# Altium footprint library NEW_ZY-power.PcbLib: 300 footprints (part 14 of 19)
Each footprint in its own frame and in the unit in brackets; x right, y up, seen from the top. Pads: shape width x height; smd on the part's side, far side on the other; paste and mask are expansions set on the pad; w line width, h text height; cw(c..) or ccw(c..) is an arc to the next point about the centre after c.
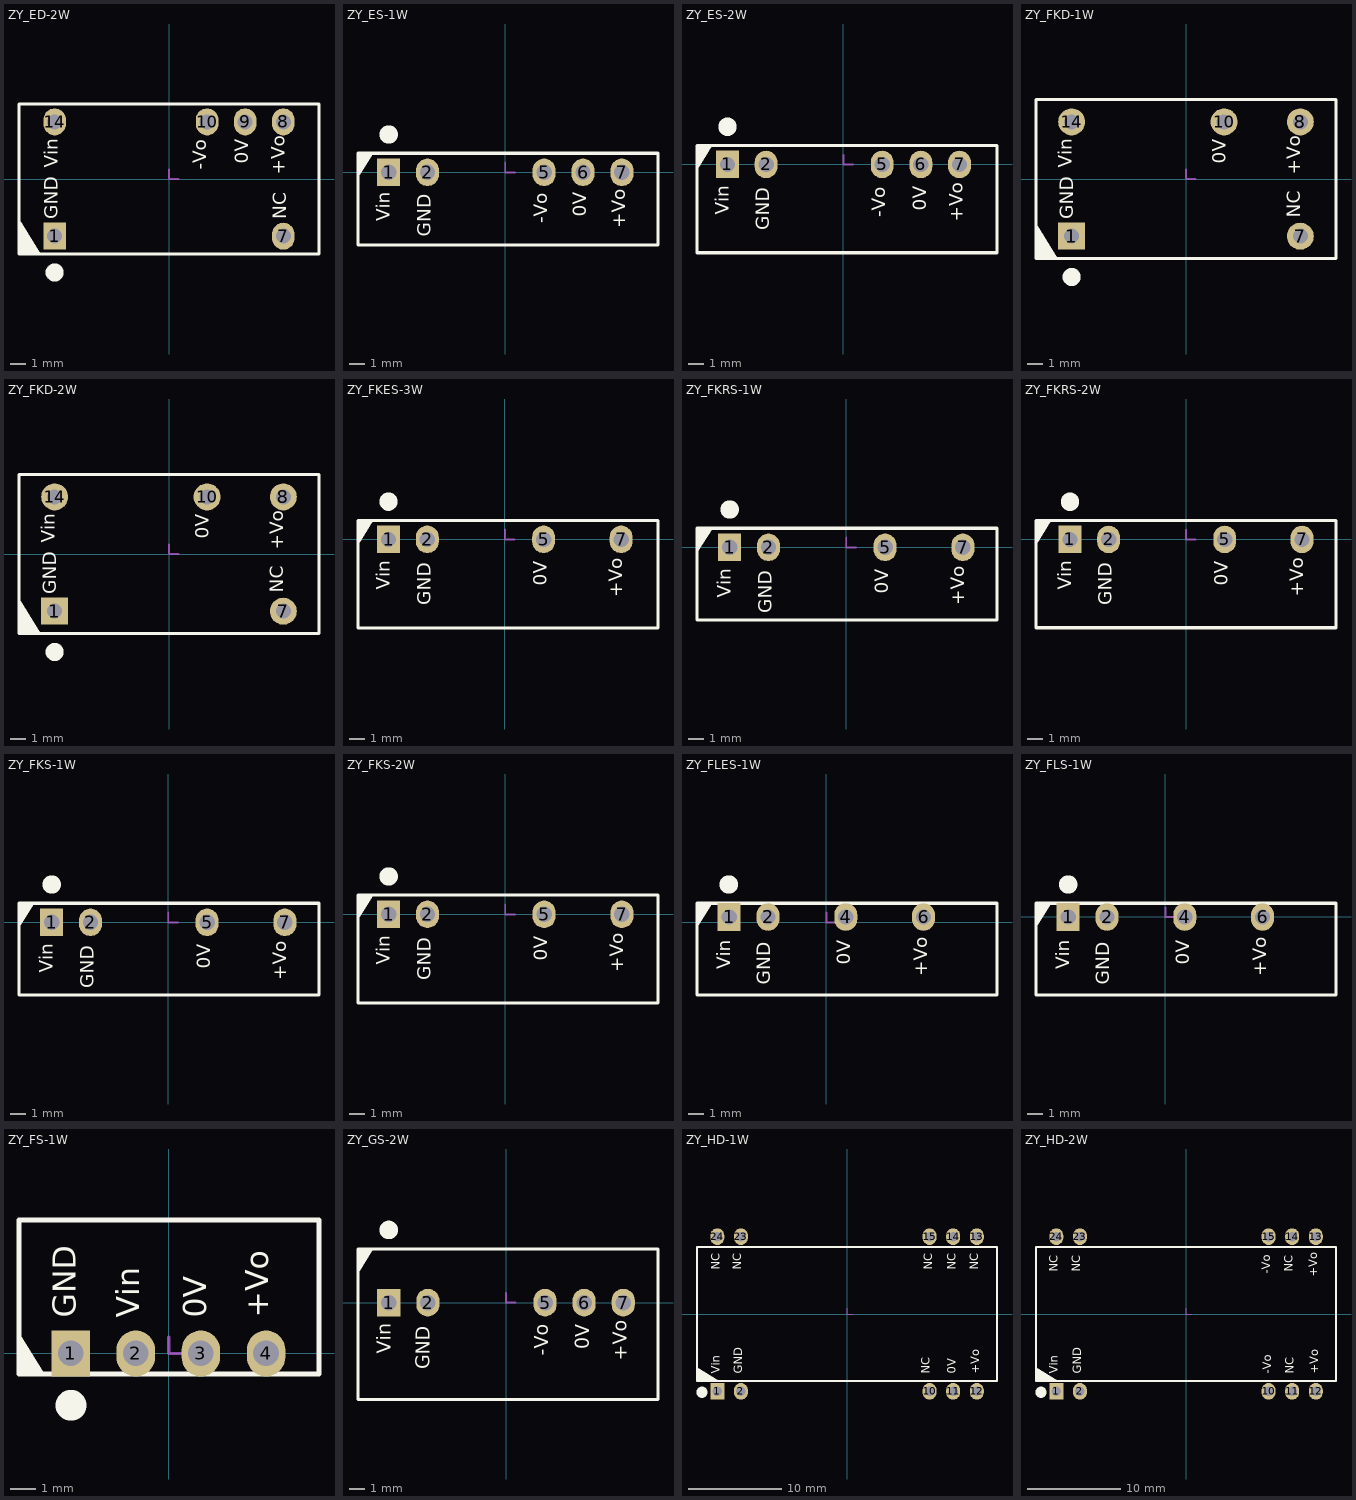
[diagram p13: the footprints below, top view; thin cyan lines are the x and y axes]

## ZY_ED-2W [mm]
height 8
pads (6):
  rect 1.5x1.8 hole 1: 1(-7.62,-3.81)
  oval 1.5x1.8 hole 1: 7(7.62,-3.81) 8(7.62,3.81) 9(5.08,3.81) 10(2.54,3.81) 14(-7.62,3.81)
Top Overlay:
  circle w1: c-7.62,-6.225 r0.1
  region: -10,-2.67 -10,-5 -8.54,-5
  lines w0.2: -10,-5 10,-5 10,5 -10,5 -10,-5
  text "+Vo" at 8.001,0.294 h1.52
  text "0V" at 5.588,1.034 h1.52
  text "-Vo" at 2.794,0.606 h1.52
  text "Vin" at -7.112,0.762 h1.52
  text "NC" at 8.128,-2.667 h1.52
  text "GND" at -7.112,-2.667 h1.52
Mechanical 15:
  lines w0.127: 0,0.635 0,0 0.635,0

## ZY_ES-1W [mm] "定压输入隔离非稳压正、负输出"
height 10
pads (5):
  rect 1.5x1.8 hole 1: 1(-7.62,0)
  oval 1.5x1.8 hole 1: 2(-5.08,0) 5(2.54,0) 6(5.08,0) 7(7.62,0)
Top Overlay:
  circle w1: c-7.62,2.475 r0.1
  region: -9.62,-0.336 -9.62,1.25 -8.626,1.25
  lines w0.2: -9.62,-4.75 9.98,-4.75 9.98,1.25 -9.62,1.25 -9.62,-4.75
  text "Vin" at -7.239,-3.181 h1.52
  text "GND" at -4.572,-4.191 h1.52
  text "-Vo" at 3.048,-3.337 h1.52
  text "0V" at 5.588,-2.909 h1.52
  text "+Vo" at 8.128,-3.649 h1.52
Mechanical 15:
  lines w0.127: 0,0.635 0,0 0.635,0

## ZY_ES-2W [mm] "定压输入隔离非稳压双输出"
height 10
pads (5):
  rect 1.5x1.8 hole 1: 1(-7.62,0)
  oval 1.5x1.8 hole 1: 2(-5.08,0) 5(2.54,0) 6(5.08,0) 7(7.62,0)
Top Overlay:
  circle w1: c-7.62,2.475 r0.1
  region: -9.62,-0.336 -9.62,1.25 -8.626,1.25
  lines w0.2: -9.62,-5.8 -9.62,1.25 10.08,1.25 10.08,-5.8 -9.62,-5.8
  text "+Vo" at 8.128,-3.776 h1.52
  text "0V" at 5.715,-3.036 h1.52
  text "-Vo" at 3.048,-3.464 h1.52
  text "GND" at -4.572,-4.318 h1.52
  text "Vin" at -7.239,-3.308 h1.52
Mechanical 15:
  lines w0.127: 0,0.635 0,0 0.635,0

## ZY_FKD-1W [mm]
height 8
pads (5):
  rect 1.8x1.8 hole 1: 1(-7.62,-3.81)
  round 1.8 hole 1: 7(7.62,-3.81) 8(7.62,3.81) 10(2.54,3.81) 14(-7.62,3.81)
Top Overlay:
  circle w1: c-7.62,-6.525 r0.1
  region: -10,-2.97 -10,-5.3 -8.54,-5.3
  lines w0.2: -10,-5.3 -10,5.3 10,5.3 10,-5.3 -10,-5.3
  text "+Vo" at 7.925,0.286 h1.52
  text "0V" at 2.946,1.026 h1.52
  text "Vin" at -7.315,0.754 h1.52
  text "NC" at 7.925,-2.565 h1.52
  text "GND" at -7.214,-2.692 h1.52
Mechanical 15:
  lines w0.127: 0,0.635 0,0 0.635,0

## ZY_FKD-2W [mm]
height 8.1
pads (5):
  rect 1.8x1.8 hole 1: 1(-7.62,-3.81)
  round 1.8 hole 1: 7(7.62,-3.81) 8(7.62,3.81) 10(2.54,3.81) 14(-7.62,3.81)
Top Overlay:
  circle w1: c-7.62,-6.525 r0.1
  region: -10,-2.97 -10,-5.3 -8.54,-5.3
  lines w0.2: -10,-5.3 -10,5.3 10,5.3 10,-5.3 -10,-5.3
  text "+Vo" at 7.925,0.286 h1.52
  text "0V" at 2.946,1.026 h1.52
  text "Vin" at -7.315,0.754 h1.52
  text "NC" at 7.925,-2.565 h1.52
  text "GND" at -7.214,-2.692 h1.52
Mechanical 15:
  lines w0.127: 0,0.635 0,0 0.635,0

## ZY_FKES-3W [mm]
pads (4):
  rect 1.5x1.8 hole 1: 1(-7.62,0)
  oval 1.5x1.8 hole 1: 2(-5.08,0) 5(2.54,0) 7(7.62,0)
Top Overlay:
  circle w1: c-7.62,2.475 r0.1
  region: -9.62,-0.336 -9.62,1.25 -8.626,1.25
  lines w0.2: 10.03,-5.797 10.03,1.25 -9.62,1.25 -9.62,-5.8 10.033,-5.8
  text "Vin" at -7.239,-3.308 h1.52
  text "GND" at -4.572,-4.318 h1.52
  text "0V" at 3.048,-3.036 h1.52
  text "+Vo" at 8.001,-3.776 h1.52
Mechanical 15:
  lines w0.127: 0,0.635 0,0 0.635,0

## ZY_FKRS-1W [mm]
height 10
pads (4):
  rect 1.5x1.8 hole 1: 1(-7.62,0)
  oval 1.5x1.8 hole 1: 2(-5.08,0) 5(2.54,0) 7(7.62,0)
Top Overlay:
  circle w1: c-7.62,2.475 r0.1
  region: -9.722,-0.336 -9.722,1.25 -8.728,1.25
  lines w0.2: -9.75,-4.75 -9.75,1.25 9.85,1.25 9.85,-4.75 -9.75,-4.75
  text "Vin" at -7.239,-3.308 h1.52
  text "GND" at -4.572,-4.318 h1.52
  text "0V" at 3.048,-3.036 h1.52
  text "+Vo" at 8.001,-3.776 h1.52
Mechanical 15:
  lines w0.127: 0,0.635 0,0 0.635,0

## ZY_FKRS-2W [mm]
height 10
pads (4):
  rect 1.5x1.8 hole 1: 1(-7.62,0)
  oval 1.5x1.8 hole 1: 2(-5.08,0) 5(2.54,0) 7(7.62,0)
Top Overlay:
  circle w1: c-7.62,2.475 r0.1
  region: -9.85,-0.336 -9.85,1.25 -8.856,1.25
  lines w0.2: -9.85,-5.8 9.85,-5.8 9.85,1.25 -9.85,1.25 -9.85,-5.8
  text "+Vo" at 8.001,-3.776 h1.52
  text "0V" at 3.048,-3.036 h1.52
  text "GND" at -4.572,-4.318 h1.52
  text "Vin" at -7.239,-3.308 h1.52
Mechanical 15:
  lines w0.127: 0,0.635 0,0 0.635,0

## ZY_FKS-1W [mm]
height 10
pads (4):
  rect 1.5x1.8 hole 1: 1(-7.62,0)
  oval 1.5x1.8 hole 1: 2(-5.08,0) 5(2.54,0) 7(7.62,0)
Top Overlay:
  circle w1: c-7.62,2.475 r0.1
  region: -9.75,-0.336 -9.75,1.25 -8.756,1.25
  lines w0.2: -9.75,-4.75 9.85,-4.75 9.85,1.25 -9.75,1.25 -9.75,-4.75
  text "Vin" at -7.239,-3.308 h1.52
  text "GND" at -4.572,-4.318 h1.52
  text "0V" at 3.048,-3.036 h1.52
  text "+Vo" at 8.001,-3.776 h1.52
Mechanical 15:
  lines w0.127: 0,0.635 0,0 0.635,0

## ZY_FKS-2W [mm] "定压输入隔离非稳压单输出"
height 10
pads (4):
  rect 1.5x1.8 hole 1: 1(-7.62,0)
  oval 1.5x1.8 hole 1: 2(-5.08,0) 5(2.54,0) 7(7.62,0)
Top Overlay:
  circle w1: c-7.62,2.475 r0.1
  region: -9.62,-0.336 -9.62,1.25 -8.626,1.25
  lines w0.2: -9.62,-5.8 -9.62,1.25 9.98,1.25 9.98,-5.8 -9.62,-5.8
  text "+Vo" at 8.001,-3.776 h1.52
  text "0V" at 3.048,-3.036 h1.52
  text "GND" at -4.572,-4.318 h1.52
  text "Vin" at -7.239,-3.308 h1.52
Mechanical 15:
  lines w0.127: 0,0.635 0,0 0.635,0

## ZY_FLES-1W [mm]
height 10.1
pads (4):
  rect 1.5x1.8 hole 1: 1(-6.35,0.35)
  oval 1.5x1.8 hole 1: 2(-3.81,0.35) 4(1.27,0.35) 6(6.35,0.35)
Top Overlay:
  circle w1: c-6.374,2.475 r0.1
  region: -8.45,-0.336 -8.45,1.25 -7.456,1.25
  lines w0.2: -8.45,-4.75 -8.45,1.25 11.15,1.25 11.15,-4.75 -8.45,-4.75
  text "Vin" at -5.969,-3.054 h1.52
  text "GND" at -3.378,-4.064 h1.52
  text "0V" at 1.854,-2.782 h1.52
  text "+Vo" at 6.883,-3.522 h1.52
Mechanical 15:
  lines w0.127: 0,0.635 0,0 0.635,0

## ZY_FLS-1W [mm]
height 10
pads (4):
  rect 1.5x1.8 hole 1: 1(-6.35,0)
  oval 1.5x1.8 hole 1: 2(-3.81,0) 4(1.27,0) 6(6.35,0)
Top Overlay:
  circle w1: c-6.35,2.125 r0.1
  region: -8.45,-0.686 -8.45,0.9 -7.456,0.9
  lines w0.2: -8.45,-5.1 11.15,-5.1 11.15,0.9 -8.45,0.9 -8.45,-5.1
  text "Vin" at -5.969,-3.404 h1.52
  text "GND" at -3.378,-4.414 h1.52
  text "0V" at 1.854,-3.132 h1.52
  text "+Vo" at 6.883,-3.872 h1.52
Mechanical 15:
  lines w0.127: 0,0.635 0,0 0.635,0

## ZY_FS-1W [mm] "定压输入隔离非稳压单输出"
height 10
pads (4):
  rect 1.5x1.8 hole 1: 1(-3.823,0)
  oval 1.5x1.8 hole 1: 2(-1.283,0) 3(1.257,0) 4(3.797,0)
Top Overlay:
  circle w1: c-3.81,-2.025 r0.1
  region: -5.837,0.786 -5.837,-0.8 -4.844,-0.8
  lines w0.2: -5.837,-0.8 -5.837,5.2 5.863,5.2 5.863,-0.8 -5.837,-0.8
  text "GND" at -3.34,1.396 h1.52
  text "Vin" at -0.851,1.397 h1.52
  text "0V" at 1.765,1.396 h1.52
  text "+Vo" at 4.178,1.396 h1.52
Mechanical 15:
  lines w0.127: 0,0.635 0,0 0.635,0

## ZY_GS-2W [mm]
pads (5):
  rect 1.5x1.8 hole 1 unplated: 1(-7.62,0)
  oval 1.5x1.8 hole 1 unplated: 2(-5.08,0) 5(2.54,0) 6(5.08,0) 7(7.62,0)
Top Overlay:
  circle w1: c-7.62,4.725 r0.1
  region: -9.62,1.914 -9.62,3.5 -8.626,3.5
  lines w0.2: -9.62,-6.3 9.88,-6.3 9.88,3.5 -9.62,3.5 -9.62,-6.3
  text "Vin" at -7.207,-3.308 h1.52
  text "GND" at -4.667,-4.318 h1.52
  text "0V" at 5.715,-3.036 h1.52
  text "-Vo" at 3.048,-3.464 h1.52
  text "+Vo" at 8.128,-3.776 h1.52
Mechanical 15:
  lines w0.127: 0,0.635 0,0 0.635,0

## ZY_HD-1W [mm]
pads (10):
  rect 1.5x1.8 hole 1: 1(-13.97,-8.325)
  oval 1.5x1.8 hole 1: 2(-11.43,-8.325) 10(8.89,-8.325) 11(11.43,-8.325) 12(13.97,-8.325) 13(13.97,8.325) 14(11.43,8.325) 15(8.89,8.325) 23(-11.43,8.325) 24(-13.97,8.325)
Top Overlay:
  circle w1: c-15.621,-8.425 r0.1
  region: -13.824,-7.2 -16.154,-7.2 -16.154,-5.74
  lines w0.2: -16.154,-7.2 -16.154,7.2 16.146,7.2 16.146,-7.2 -16.154,-7.2
  text "Vin" at -13.36,-6.42 h1.52
  text "GND" at -10.947,-6.421 h1.52
  text "NC" at 9.246,-6.421 h1.52
  text "0V" at 12.04,-6.421 h1.52
  text "+Vo" at 14.58,-6.421 h1.52
  text "NC" at 9.5,4.769 h1.52
  text "NC" at 12.04,4.769 h1.52
  text "NC" at 14.453,4.769 h1.52
  text "NC" at -11.074,4.769 h1.52
  text "NC" at -13.36,4.769 h1.52
Mechanical 15:
  lines w0.127: 0,0.635 0,0 0.635,0

## ZY_HD-2W [mm]
pads (10):
  rect 1.5x1.8 hole 1: 1(-13.97,-8.325)
  oval 1.5x1.8 hole 1: 2(-11.43,-8.325) 10(8.89,-8.325) 11(11.43,-8.325) 12(13.97,-8.325) 13(13.97,8.325) 14(11.43,8.325) 15(8.89,8.325) 23(-11.43,8.325) 24(-13.97,8.325)
Top Overlay:
  circle w1: c-15.621,-8.425 r0.1
  region: -13.824,-7.2 -16.154,-7.2 -16.154,-5.74
  lines w0.2: -16.154,-7.2 -16.154,7.2 16.146,7.2 16.146,-7.2 -16.154,-7.2
  text "+Vo" at 14.453,4.007 h1.52
  text "-Vo" at 9.373,4.319 h1.52
  text "NC" at 11.786,4.536 h1.52
  text "NC" at 11.913,-6.421 h1.52
  text "-Vo" at 9.5,-6.421 h1.52
  text "Vin" at -13.487,-6.42 h1.52
  text "GND" at -10.947,-6.421 h1.52
  text "+Vo" at 14.58,-6.421 h1.52
  text "NC" at -11.074,4.536 h1.52
  text "NC" at -13.487,4.536 h1.52
Mechanical 15:
  lines w0.127: 0,0.635 0,0 0.635,0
